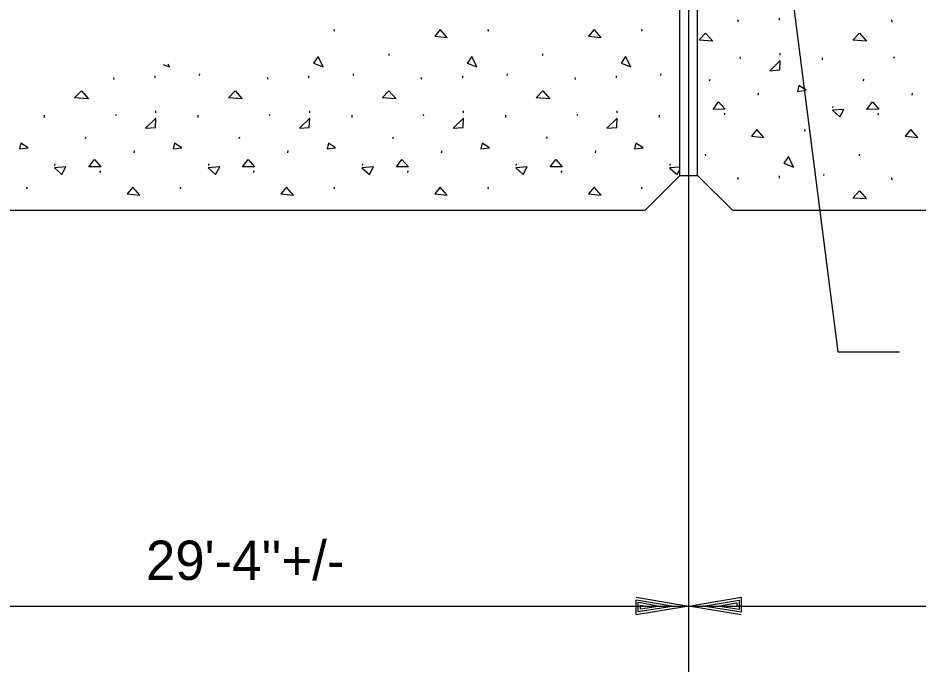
# Model space of a CAD drawing. Extents: x 22369.6 to 22384.3, y 22369.6 to 22381.8.
# Drawn here: x 22371.507 to 22372.573, y 22378.065 to 22378.84 of the extents above; entities that cross this region are included whole.
import ezdxf

# ---------------------------------------------------------------- set-up
doc = ezdxf.new("R2010")
doc.units = 0
for name, color, linetype in [('Level 1', 7, 'Continuous'), ('Level 10', 7, 'Continuous'), ('Level 4', 7, 'Continuous'), ('Level 8', 7, 'Continuous')]:
    doc.layers.add(name, color=color, linetype=linetype)

msp = doc.modelspace()

# ---------------------------------------------------------------- linework, layer by layer
at = {"layer": 'Level 1'}
for p, q in [((22372.3014, 22378.0649), (22372.3014, 22379.6682)), ((22372.3947, 22379.0988), (22372.4782, 22378.4445)), ((22372.4782, 22378.4445), (22372.5513, 22378.4445)), ((22371.2877, 22378.1431), (22372.3014, 22378.1431)), ((22372.2841, 22378.1431), (22372.2841, 22378.1431)), ((22372.3014, 22378.1431), (22372.3014, 22378.1431)), ((22372.3014, 22378.1431), (22372.3014, 22378.1431)), ((22372.3014, 22378.1431), (22374.1817, 22378.1431)), ((22372.3187, 22378.1431), (22372.3187, 22378.1431))]:
    msp.add_line(p, q, dxfattribs=at)
for points in [[(22372.2876, 22378.6547), (22372.291, 22378.6611)], [(22372.2391, 22378.1535), (22372.3014, 22378.1431), (22372.2391, 22378.1328), (22372.2391, 22378.1505), (22372.2841, 22378.1431), (22372.2417, 22378.1361), (22372.2417, 22378.1475), (22372.2674, 22378.1431), (22372.2444, 22378.1395), (22372.2444, 22378.1441), (22372.2501, 22378.1431)], [(22372.3637, 22378.1328), (22372.3014, 22378.1431), (22372.3637, 22378.1535), (22372.3637, 22378.1358), (22372.3187, 22378.1431), (22372.3611, 22378.1501), (22372.3611, 22378.1388), (22372.3354, 22378.1431), (22372.3584, 22378.1468), (22372.3584, 22378.1421), (22372.3527, 22378.1431)]]:
    msp.add_lwpolyline(points, dxfattribs=at)
at = {"layer": 'Level 10'}
for p, q in [((22372.291, 22378.6536), (22372.291, 22379.0822)), ((22372.3118, 22378.6536), (22372.3118, 22379.0822)), ((22372.2493, 22378.6119), (22372.291, 22378.6536)), ((22372.291, 22378.6536), (22372.3118, 22378.6536)), ((22372.3535, 22378.6119), (22372.3118, 22378.6536)), ((22372.2493, 22378.6119), (22371.2877, 22378.6119)), ((22373.6529, 22378.6119), (22372.3535, 22378.6119))]:
    msp.add_line(p, q, dxfattribs=at)
at = {"layer": 'Level 8'}
for p, q in [((22372.3604, 22378.8354), (22372.3597, 22378.8379)), ((22372.4089, 22378.8374), (22372.4089, 22378.8399)), ((22372.5426, 22378.8354), (22372.5419, 22378.8379)), ((22371.8823, 22378.8245), (22371.8811, 22378.8267)), ((22372.0645, 22378.8245), (22372.0633, 22378.8267)), ((22372.2467, 22378.8245), (22372.2456, 22378.8267)), ((22372.4098, 22378.796), (22372.4098, 22378.7983)), ((22371.9464, 22378.7955), (22371.9463, 22378.7975)), ((22372.1286, 22378.7955), (22372.1285, 22378.7975)), ((22372.3629, 22378.7923), (22372.3622, 22378.7941)), ((22372.4599, 22378.7906), (22372.4599, 22378.7931)), ((22372.5451, 22378.7923), (22372.5444, 22378.7941)), ((22371.6208, 22378.7671), (22371.6201, 22378.7696)), ((22371.6693, 22378.7691), (22371.6693, 22378.7716)), ((22371.7218, 22378.7721), (22371.7222, 22378.774)), ((22371.803, 22378.7671), (22371.8023, 22378.7696)), ((22371.8515, 22378.7691), (22371.8515, 22378.7716)), ((22371.9041, 22378.7721), (22371.9044, 22378.774)), ((22371.9852, 22378.7671), (22371.9845, 22378.7696)), ((22372.0337, 22378.7691), (22372.0337, 22378.7716)), ((22372.0863, 22378.7721), (22372.0866, 22378.774)), ((22372.1674, 22378.7671), (22372.1667, 22378.7696)), ((22372.2159, 22378.7691), (22372.2159, 22378.7716)), ((22372.2685, 22378.7721), (22372.2688, 22378.774)), ((22372.3261, 22378.7656), (22372.327, 22378.7676)), ((22372.5083, 22378.7656), (22372.5092, 22378.7676)), ((22372.3839, 22378.7488), (22372.3843, 22378.7512)), ((22372.5661, 22378.7488), (22372.5665, 22378.7512)), ((22372.4723, 22378.7336), (22372.4725, 22378.7354)), ((22371.5381, 22378.7223), (22371.5381, 22378.7248)), ((22371.6233, 22378.724), (22371.6226, 22378.7258)), ((22371.6702, 22378.7277), (22371.6702, 22378.73)), ((22371.7203, 22378.7223), (22371.7203, 22378.7248)), ((22371.8055, 22378.724), (22371.8048, 22378.7258)), ((22371.8524, 22378.7277), (22371.8524, 22378.73)), ((22371.9025, 22378.7223), (22371.9025, 22378.7248)), ((22371.9877, 22378.724), (22371.987, 22378.7258)), ((22372.0346, 22378.7277), (22372.0346, 22378.73)), ((22372.0847, 22378.7223), (22372.0847, 22378.7248)), ((22372.1699, 22378.724), (22372.1692, 22378.7258)), ((22372.2168, 22378.7277), (22372.2168, 22378.73)), ((22372.2669, 22378.7223), (22372.2669, 22378.7248)), ((22372.3433, 22378.7253), (22372.3446, 22378.7273)), ((22372.5255, 22378.7253), (22372.5268, 22378.7273)), ((22372.4397, 22378.7058), (22372.4386, 22378.708)), ((22371.5865, 22378.6973), (22371.5874, 22378.6993)), ((22371.7687, 22378.6973), (22371.7696, 22378.6993)), ((22371.9509, 22378.6973), (22371.9518, 22378.6993)), ((22372.1331, 22378.6973), (22372.134, 22378.6993)), ((22371.6443, 22378.6805), (22371.6447, 22378.6829)), ((22371.8265, 22378.6805), (22371.8269, 22378.6829)), ((22372.0087, 22378.6805), (22372.0091, 22378.6829)), ((22372.1909, 22378.6805), (22372.1913, 22378.6829)), ((22372.3216, 22378.6767), (22372.3215, 22378.6788)), ((22372.5038, 22378.6767), (22372.5037, 22378.6788)), ((22371.5505, 22378.6653), (22371.5506, 22378.6671)), ((22371.7327, 22378.6653), (22371.7328, 22378.6671)), ((22371.9149, 22378.6653), (22371.9151, 22378.6671)), ((22372.0971, 22378.6653), (22372.0973, 22378.6671)), ((22372.2793, 22378.6653), (22372.2795, 22378.6671)), ((22371.6037, 22378.657), (22371.6049, 22378.6591)), ((22371.7859, 22378.657), (22371.7871, 22378.6591)), ((22371.9681, 22378.657), (22371.9693, 22378.6591)), ((22372.1503, 22378.657), (22372.1516, 22378.6591)), ((22372.3604, 22378.6484), (22372.3597, 22378.6509)), ((22372.4089, 22378.6504), (22372.4089, 22378.6529)), ((22372.4615, 22378.6533), (22372.4618, 22378.6552)), ((22372.5426, 22378.6484), (22372.5419, 22378.6509)), ((22371.5178, 22378.6375), (22371.5167, 22378.6397)), ((22371.7001, 22378.6375), (22371.6989, 22378.6397)), ((22371.8823, 22378.6375), (22371.8811, 22378.6397)), ((22372.0645, 22378.6375), (22372.0633, 22378.6397)), ((22372.2467, 22378.6375), (22372.2456, 22378.6397))]:
    msp.add_line(p, q, dxfattribs=at)
for points in [[(22372.0153, 22378.817), (22372.0071, 22378.8265), (22372.0005, 22378.8186)], [(22372.1976, 22378.817), (22372.1893, 22378.8265), (22372.1827, 22378.8186)], [(22372.4957, 22378.8137), (22372.5036, 22378.8223), (22372.5121, 22378.8128)], [(22371.8569, 22378.7866), (22371.8683, 22378.7822), (22371.8623, 22378.7945)], [(22372.0391, 22378.7866), (22372.0505, 22378.7822), (22372.0445, 22378.7945)], [(22372.2213, 22378.7866), (22372.2327, 22378.7822), (22372.2267, 22378.7945)], [(22372.4092, 22378.7786), (22372.4098, 22378.7897), (22372.3975, 22378.7777)], [(22372.4303, 22378.7532), (22372.4404, 22378.7545), (22372.4319, 22378.7602)], [(22371.5738, 22378.7454), (22371.5818, 22378.754), (22371.5903, 22378.7445)], [(22371.7561, 22378.7454), (22371.764, 22378.754), (22371.7725, 22378.7445)], [(22371.9383, 22378.7454), (22371.9462, 22378.754), (22371.9547, 22378.7445)], [(22372.1205, 22378.7454), (22372.1284, 22378.754), (22372.1369, 22378.7445)], [(22372.3302, 22378.7318), (22372.3369, 22378.7407), (22372.3445, 22378.7322)], [(22372.5124, 22378.7318), (22372.5191, 22378.7407), (22372.5267, 22378.7322)], [(22372.4717, 22378.7309), (22372.4806, 22378.723), (22372.4853, 22378.7318)], [(22371.6696, 22378.7103), (22371.6702, 22378.7214), (22371.6578, 22378.7094)], [(22371.8518, 22378.7103), (22371.8524, 22378.7214), (22371.8401, 22378.7094)], [(22372.034, 22378.7103), (22372.0346, 22378.7214), (22372.0223, 22378.7094)], [(22372.2162, 22378.7103), (22372.2168, 22378.7214), (22372.2045, 22378.7094)], [(22372.3906, 22378.6983), (22372.3823, 22378.7078), (22372.3757, 22378.6999)], [(22372.5728, 22378.6983), (22372.5645, 22378.7078), (22372.5579, 22378.6999)], [(22371.5085, 22378.6849), (22371.5186, 22378.6862), (22371.5101, 22378.6919)], [(22371.6907, 22378.6849), (22371.7008, 22378.6862), (22371.6923, 22378.6919)], [(22371.8729, 22378.6849), (22371.883, 22378.6862), (22371.8745, 22378.6919)], [(22372.0551, 22378.6849), (22372.0652, 22378.6862), (22372.0567, 22378.6919)], [(22372.2373, 22378.6849), (22372.2474, 22378.6862), (22372.2389, 22378.6919)], [(22371.5906, 22378.6636), (22371.5973, 22378.6724), (22371.6048, 22378.6639)], [(22371.7728, 22378.6636), (22371.7795, 22378.6724), (22371.7871, 22378.6639)], [(22371.955, 22378.6636), (22371.9617, 22378.6724), (22371.9693, 22378.6639)], [(22372.1372, 22378.6636), (22372.1439, 22378.6724), (22372.1515, 22378.6639)], [(22372.4143, 22378.6679), (22372.4257, 22378.6635), (22372.4197, 22378.6758)], [(22371.5498, 22378.6626), (22371.5587, 22378.6547), (22371.5635, 22378.6636)], [(22371.7321, 22378.6626), (22371.7409, 22378.6547), (22371.7457, 22378.6636)], [(22371.9143, 22378.6626), (22371.9231, 22378.6547), (22371.9279, 22378.6636)], [(22372.0965, 22378.6626), (22372.1053, 22378.6547), (22372.1101, 22378.6636)], [(22371.6509, 22378.63), (22371.6427, 22378.6395), (22371.6361, 22378.6316)], [(22371.8331, 22378.63), (22371.8249, 22378.6395), (22371.8183, 22378.6316)], [(22372.0153, 22378.63), (22372.0071, 22378.6395), (22372.0005, 22378.6316)], [(22372.1976, 22378.63), (22372.1893, 22378.6395), (22372.1827, 22378.6316)], [(22372.4957, 22378.6267), (22372.5036, 22378.6353), (22372.5121, 22378.6258)]]:
    msp.add_lwpolyline(points, close=True, dxfattribs=at)
for points in [[(22372.3139, 22378.8142), (22372.3214, 22378.8223)], [(22372.3214, 22378.8223), (22372.3299, 22378.8128)], [(22372.3299, 22378.8128), (22372.3139, 22378.8137)], [(22371.6789, 22378.785), (22371.6861, 22378.7822)], [(22371.6861, 22378.7822), (22371.6845, 22378.7856)], [(22372.291, 22378.6635), (22372.2787, 22378.6626)], [(22372.2787, 22378.6626), (22372.2876, 22378.6547)]]:
    msp.add_lwpolyline(points, dxfattribs=at)

# ---------------------------------------------------------------- texts
at = {"layer": 'Level 4'}
msp.add_text("29'-4''+/-", height=0.04663, dxfattribs=at).set_placement((22371.6584, 22378.174))

doc.saveas('drawing.dxf')
